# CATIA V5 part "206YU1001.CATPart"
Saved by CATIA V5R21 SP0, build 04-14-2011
Part number: 206YU1001
Bounding box of the stored display mesh (mm): x -37.274 to -7.274, y -47.418 to -17.418, z 0 to 82.5
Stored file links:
  C:\Users\ALI OZGUN\Desktop\alhan\206YU1001.CATPart
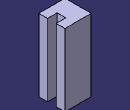
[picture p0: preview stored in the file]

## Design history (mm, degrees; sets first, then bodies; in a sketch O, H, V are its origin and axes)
Set1
  DatumSurface1 to DatumSurface10
  Join1: Elements (DatumSurface2; DatumSurface10; DatumSurface1; DatumSurface7; DatumSurface5; DatumSurface8; DatumSurface9; DatumSurface4; DatumSurface3; DatumSurface6)
Body1 (main body)
  CloseSurface1: CloseElement Join1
